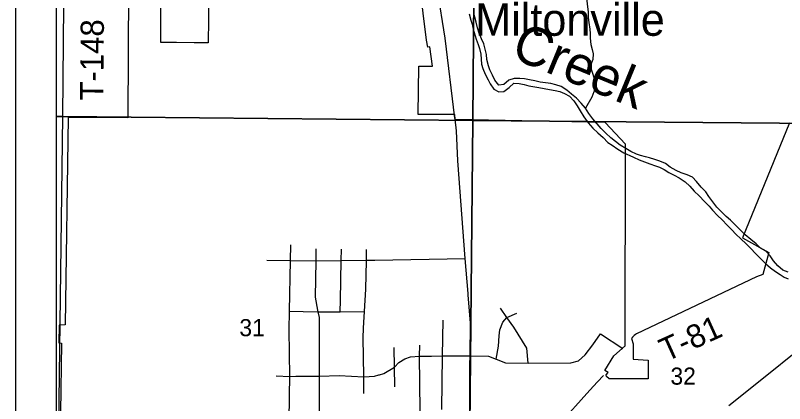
# Model space of a CAD drawing. Extents: x 0 to 34, y 0 to 22.
# Drawn here: x 2 to 3.881, y 15.439 to 16.387 of the extents above; entities that cross this region are included whole.
import ezdxf

# ---------------------------------------------------------------- set-up
doc = ezdxf.new("R2010")
doc.units = 0
for name, color, linetype in [('GM_X_City_Street', 7, 'Continuous'), ('GM_X_Corporation', 7, 'Continuous'), ('GM_X_County_Road', 7, 'Continuous'), ('GM_X_Minor_River', 7, 'Continuous'), ('GM_X_Minor_River_Text', 7, 'Continuous'), ('GM_X_Rail_Line', 7, 'Continuous'), ('GM_X_Section_Text', 7, 'Continuous'), ('GM_X_Township_Road_Text', 7, 'Continuous'), ('GM_X_Unincorporated_Text', 7, 'Continuous'), ('SH_Data', 7, 'Continuous')]:
    doc.layers.add(name, color=color, linetype=linetype)

msp = doc.modelspace()

# ---------------------------------------------------------------- linework, layer by layer
at = {"layer": 'GM_X_City_Street'}
for p, q in [((2.8791, 15.7894), (3.0997, 15.7929)), ((3.4312, 15.6092), (3.4854, 15.5735))]:
    msp.add_line(p, q, dxfattribs=at)
for points in [[(2.6675, 15.1326), (2.6692, 15.2644), (2.6684, 15.3298), (2.6702, 15.4583), (2.6708, 15.505), (2.6696, 15.619), (2.6704, 15.6647), (2.6727, 15.7883), (2.6734, 15.8265)], [(2.7438, 15.1333), (2.7445, 15.1633), (2.7438, 15.2749), (2.7436, 15.3289), (2.7435, 15.5056), (2.7435, 15.633), (2.7435, 15.6494), (2.7406, 15.6626), (2.7396, 15.6671), (2.7337, 15.6987), (2.7352, 15.7871), (2.7357, 15.8167)], [(2.7943, 15.6632), (2.7951, 15.6912), (2.7967, 15.7881), (2.7971, 15.8159)], [(2.8514, 15.6228), (2.8518, 15.6366), (2.8537, 15.6639), (2.8567, 15.7183), (2.8587, 15.7872), (2.8587, 15.7891), (2.8587, 15.8148)], [(2.615, 15.7891), (2.6727, 15.7883), (2.7352, 15.7871), (2.7967, 15.7881), (2.8587, 15.7891), (2.8791, 15.7894)], [(3.254, 15.5377), (3.2503, 15.5743), (3.2189, 15.6253), (3.2021, 15.6489), (3.1859, 15.6718)], [(2.6704, 15.6647), (2.7034, 15.6636), (2.7406, 15.6626), (2.7943, 15.6632), (2.8537, 15.6639)], [(3.1754, 15.5473), (3.1814, 15.5788), (3.1829, 15.6043), (3.1844, 15.6193), (3.1919, 15.6373), (3.2021, 15.6489), (3.2264, 15.6598)], [(3.0429, 15.4242), (3.0448, 15.555), (3.0461, 15.6428)], [(2.8518, 15.4634), (2.8518, 15.504), (2.8518, 15.5057), (2.8508, 15.5993), (2.8514, 15.6228)], [(3.1118, 15.5552), (3.1569, 15.5547), (3.1754, 15.5473), (3.1989, 15.538), (3.254, 15.5377), (3.358, 15.5382), (3.3772, 15.5435), (3.3933, 15.558), (3.4124, 15.5826), (3.4312, 15.6092)], [(2.928, 15.4794), (2.927, 15.5278), (2.926, 15.5759)], [(2.9879, 15.2619), (2.9899, 15.4219), (2.9882, 15.5544), (2.9887, 15.5811)], [(2.8906, 15.5092), (2.9014, 15.5119), (2.927, 15.5278), (2.9374, 15.539), (2.9524, 15.5479), (2.9662, 15.5527), (2.9882, 15.5544), (3.0175, 15.5546), (3.0448, 15.555), (3.1118, 15.5552)], [(2.6375, 15.5067), (2.6708, 15.505), (2.686, 15.5054), (2.6984, 15.5054)], [(2.6984, 15.5054), (2.7232, 15.5053), (2.7435, 15.5056), (2.792, 15.5074), (2.8518, 15.504), (2.8778, 15.506), (2.8886, 15.5087), (2.8906, 15.5092)], [(3.1506, 15.1361), (3.1512, 15.1639), (3.151, 15.1716), (3.1508, 15.1776), (3.1523, 15.1947), (3.1845, 15.2291), (3.2195, 15.2674), (3.2265, 15.2771), (3.2679, 15.3215), (3.281, 15.3362), (3.3271, 15.3851), (3.4048, 15.4712), (3.4239, 15.4916), (3.4385, 15.5071)]]:
    msp.add_lwpolyline(points, dxfattribs=at)
at = {"layer": 'GM_X_Corporation'}
for points in [[(8.2532, 20.898), (2.1, 20.898), (2.1, 14.098)], [(2.2769, 16.4548), (2.2746, 16.137), (2.1294, 16.1374), (2.1217, 15.6308), (2.1072, 15.6303), (2.1066, 15.587), (2.1127, 15.5867), (2.1107, 15.417)], [(2.473, 16.4346), (2.4716, 16.3199), (2.4374, 16.32), (2.3941, 16.3206), (2.3559, 16.3211), (2.3556, 16.4542)], [(3.8931, 16.1244), (3.7783, 15.844), (3.8422, 15.8076), (3.8275, 15.7544), (3.8124, 15.7483), (3.5186, 15.6091), (3.5163, 15.6077), (3.5134, 15.6054), (3.5088, 15.6006), (3.5065, 15.5975), (3.5104, 15.5848), (3.5104, 15.547), (3.5476, 15.5451), (3.5471, 15.4989), (3.4518, 15.4994), (3.4457, 15.5052), (3.4449, 15.5087), (3.4493, 15.5143), (3.4416, 15.5198), (3.4635, 15.5557), (3.4908, 15.5799), (3.4917, 16.0723), (3.4423, 16.1255), (3.0757, 16.1331), (3.0744, 16.1451), (2.9852, 16.1453), (2.9867, 16.2628), (3.0204, 16.2628), (3.0136, 16.3106), (3.0087, 16.3099), (3.005, 16.3267), (2.9888, 16.4591)], [(3.1092, 15.1326), (3.1186, 16.1305), (4.1502, 16.1212)]]:
    msp.add_lwpolyline(points, dxfattribs=at)
for points in [[(2.1, 17.1398), (2.1, 16.1403), (2.1158, 16.1403), (2.1252, 17.1396)], [(3.1266, 17.137), (3.1186, 16.1305), (2.1158, 16.1403), (2.1252, 17.1396)], [(4.1603, 17.1368), (4.1502, 16.1212), (3.1186, 16.1305), (3.1266, 17.137)], [(2.1, 16.1403), (2.1, 15.1304), (2.1027, 15.1304), (2.1158, 16.1403)], [(2.1158, 16.1403), (3.1186, 16.1305), (3.1092, 15.1326), (2.1027, 15.1304)]]:
    msp.add_lwpolyline(points, close=True, dxfattribs=at)
at = {"layer": 'GM_X_County_Road'}
for points in [[(3.075, 16.136), (3.0511, 16.3316), (3.0321, 16.4498), (3.0329, 16.4708), (3.0279, 16.5131)], [(3.107, 15.7075), (3.0997, 15.7929), (3.0818, 16.0321), (3.0788, 16.1051), (3.0753, 16.134), (3.075, 16.136)], [(3.1118, 15.5552), (3.1128, 15.6353), (3.1073, 15.7046), (3.107, 15.7075)], [(3.1093, 15.1371), (3.1078, 15.1674), (3.108, 15.1784), (3.11, 15.2674), (3.1101, 15.2766), (3.1116, 15.5332), (3.1118, 15.5552)]]:
    msp.add_lwpolyline(points, dxfattribs=at)
at = {"layer": 'GM_X_Minor_River'}
for points in [[(3.3911, 16.45), (3.3925, 16.4462), (3.3957, 16.4366), (3.3976, 16.4229), (3.3987, 16.4084), (3.4006, 16.3955), (3.4006, 16.3822), (3.4025, 16.3696), (3.4044, 16.3536), (3.4052, 16.3433), (3.4053, 16.3312), (3.4072, 16.3163), (3.4102, 16.3037), (3.4133, 16.293), (3.4122, 16.2797), (3.4073, 16.267), (3.4081, 16.2556), (3.4109, 16.246), (3.4144, 16.2353), (3.416, 16.225), (3.4176, 16.2132), (3.4142, 16.2004), (3.41, 16.1876), (3.3945, 16.1606)], [(3.11, 16.3911), (3.1141, 16.3754), (3.1169, 16.3659), (3.1196, 16.3537), (3.1265, 16.3288), (3.1319, 16.3161), (3.135, 16.3065), (3.138, 16.2928), (3.1388, 16.2806), (3.14, 16.2677), (3.1431, 16.257), (3.1488, 16.2432), (3.1564, 16.2297), (3.1611, 16.2201), (3.1698, 16.2069), (3.1822, 16.2005), (3.1944, 16.2013), (3.2075, 16.2108), (3.2192, 16.2212), (3.2317, 16.2208), (3.2438, 16.2182), (3.2559, 16.2152), (3.2699, 16.2126), (3.2801, 16.2108), (3.2929, 16.2085), (3.3061, 16.2063), (3.3197, 16.204), (3.3311, 16.2011), (3.3431, 16.1966), (3.3547, 16.1898), (3.3657, 16.1781), (3.3738, 16.1661), (3.3814, 16.1538), (3.3901, 16.1395), (3.4007, 16.1248), (3.4118, 16.112), (3.424, 16.1003), (3.4373, 16.0885), (3.4491, 16.0764), (3.4592, 16.0697), (3.4734, 16.0602), (3.4883, 16.0511), (3.5022, 16.045), (3.5119, 16.0406), (3.5258, 16.0341), (3.5386, 16.0292), (3.5514, 16.0247), (3.5653, 16.0194), (3.575, 16.0161), (3.5867, 16.0105), (3.5982, 16.0037), (3.6106, 15.9969), (3.6233, 15.9901), (3.6375, 15.9803), (3.649, 15.9701), (3.6596, 15.958), (3.6718, 15.9459), (3.6851, 15.9327), (3.6962, 15.921), (3.7047, 15.9113), (3.7172, 15.898), (3.7287, 15.8875), (3.7405, 15.875), (3.7523, 15.8629), (3.7615, 15.8528), (3.7737, 15.8415), (3.7871, 15.8293), (3.7981, 15.8173), (3.8096, 15.8052), (3.8229, 15.7923), (3.834, 15.7806), (3.8462, 15.7701), (3.8589, 15.7614), (3.8701, 15.7542), (3.8801, 15.7479), (3.8899, 15.7438)], [(3.8896, 15.7594), (3.8764, 15.7647), (3.8642, 15.7749), (3.8539, 15.7873), (3.8459, 15.8001), (3.8352, 15.8114), (3.8225, 15.8185), (3.8114, 15.8291), (3.7988, 15.84), (3.785, 15.8514), (3.7732, 15.8624), (3.7488, 15.8866), (3.7384, 15.8959), (3.7266, 15.9073), (3.7151, 15.9186), (3.7056, 15.9314), (3.6957, 15.9449), (3.6884, 15.9557), (3.6774, 15.9678), (3.666, 15.981), (3.6556, 15.9923), (3.6425, 15.998), (3.6282, 16.0022), (3.6155, 16.0082), (3.6016, 16.0162), (3.5897, 16.0252), (3.5762, 16.0313), (3.5638, 16.035), (3.551, 16.0388), (3.5412, 16.0413), (3.5284, 16.0451), (3.5186, 16.048), (3.5051, 16.0548), (3.4928, 16.062), (3.4793, 16.0703), (3.4678, 16.0793), (3.4559, 16.088), (3.4437, 16.0994), (3.4322, 16.1107), (3.4124, 16.1347), (3.4025, 16.1471), (3.3945, 16.1606), (3.3838, 16.1731), (3.3724, 16.1852), (3.3601, 16.1946), (3.3486, 16.2044), (3.3348, 16.2135), (3.3213, 16.2177), (3.3092, 16.2206), (3.2835, 16.2244), (3.2706, 16.227), (3.2574, 16.23), (3.2453, 16.2322), (3.2332, 16.2333), (3.2195, 16.2329), (3.2069, 16.2291), (3.1948, 16.2184), (3.1823, 16.2165), (3.1727, 16.2285), (3.167, 16.2408), (3.1601, 16.2542), (3.1566, 16.2638), (3.1532, 16.2795), (3.1517, 16.2913), (3.149, 16.3047), (3.1452, 16.3173), (3.1402, 16.3299), (3.1341, 16.3434), (3.1299, 16.3564), (3.1265, 16.3705), (3.1234, 16.3828), (3.1215, 16.3935)]]:
    msp.add_lwpolyline(points, dxfattribs=at)
at = {"layer": 'GM_X_Rail_Line'}
msp.add_lwpolyline([(3.745, 15.434), (3.8337, 15.5051), (3.9125, 15.5684)], dxfattribs=at)
at = {"layer": 'SH_Data'}
for p, q in [((2, 20.998), (2, 13.998)), ((2.1, 20.898), (2.1, 14.098))]:
    msp.add_line(p, q, dxfattribs=at)

# ---------------------------------------------------------------- texts
at = {"layer": 'GM_X_Minor_River_Text'}
msp.add_text('Creek', height=0.09469, rotation=337.595, dxfattribs=at).set_placement((3.2081, 16.2852))
at = {"layer": 'GM_X_Section_Text'}
for s, p in [('31', (2.5477, 15.6033)), ('32', (3.6019, 15.4849))]:
    msp.add_text(s, height=0.04186, rotation=0, dxfattribs=at).set_placement(p)
at = {"layer": 'GM_X_Township_Road_Text'}
for s, rotation, p in [('T-148', 89.4381, (2.2147, 16.1789)), ('T-81', 24.388, (3.5912, 15.5402))]:
    msp.add_text(s, height=0.05682, rotation=rotation, dxfattribs=at).set_placement(p)
at = {"layer": 'GM_X_Unincorporated_Text'}
msp.add_text('Miltonville', height=0.078977, rotation=0, dxfattribs=at).set_placement((3.1244, 16.3373))

doc.saveas('drawing.dxf')
